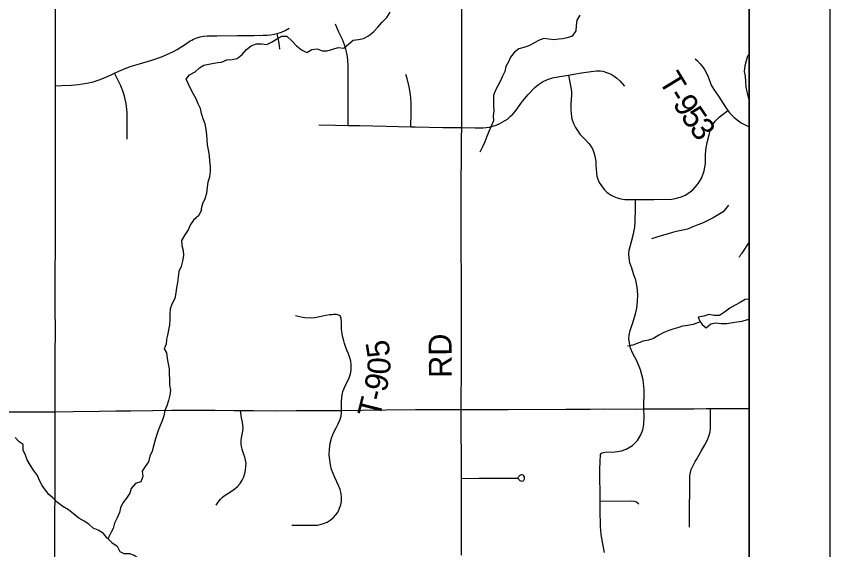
# Model space of a CAD drawing. Extents: x 0 to 34, y 0 to 22.
# Drawn here: x 7.992 to 9, y 14.845 to 15.506 of the extents above; entities that cross this region are included whole.
import ezdxf

# ---------------------------------------------------------------- set-up
doc = ezdxf.new("R2010")
doc.units = 0
for name, color, linetype in [('GM_X_County_Road', 7, 'Continuous'), ('GM_X_Minor_Lake', 7, 'Continuous'), ('GM_X_Minor_River', 7, 'Continuous'), ('GM_X_Rail_Line_Text', 7, 'Continuous'), ('GM_X_State_Route', 7, 'Continuous'), ('GM_X_Township_Road', 7, 'Continuous'), ('GM_X_Township_Road_Text', 7, 'Continuous'), ('SH_Cut_Line', 7, 'Continuous'), ('SH_Data', 7, 'Continuous')]:
    doc.layers.add(name, color=color, linetype=linetype)

msp = doc.modelspace()

# ---------------------------------------------------------------- linework, layer by layer
at = {"layer": 'GM_X_County_Road'}
msp.add_lwpolyline([(7.9697, 15.0163), (8.0251, 15.0165), (8.04, 15.0165), (8.0624, 15.0168), (8.0949, 15.0171), (8.115, 15.0174), (8.1338, 15.0177), (8.1608, 15.0181), (8.1843, 15.0183), (8.2118, 15.0183), (8.2383, 15.0182), (8.2619, 15.0181), (8.2697, 15.018), (8.2857, 15.0179), (8.3148, 15.0177), (8.339, 15.0178), (8.3602, 15.0181), (8.3808, 15.0181), (8.3948, 15.0181), (8.42, 15.0184), (8.4496, 15.0187), (8.4864, 15.019), (8.5076, 15.019), (8.5322, 15.0191), (8.5433, 15.0191), (8.5616, 15.0191), (8.6013, 15.0194), (8.6729, 15.0196), (8.7032, 15.0197), (8.7191, 15.0199), (8.7604, 15.0198), (8.7697, 15.0199), (8.7876, 15.02), (8.8317, 15.0202), (8.847, 15.0203), (8.8522, 15.0204), (8.88, 15.0206), (8.9, 15.0206)], dxfattribs=at)
at = {"layer": 'GM_X_Minor_Lake'}
for points in [[(8.9, 15.1557), (8.8951, 15.1555), (8.8889, 15.1516), (8.8827, 15.1483), (8.876, 15.1446), (8.8694, 15.1396), (8.8634, 15.1357), (8.8568, 15.1358), (8.8503, 15.1369), (8.8438, 15.1347), (8.837, 15.1335), (8.839, 15.1286)], [(8.839, 15.1286), (8.8419, 15.1246), (8.847, 15.1205), (8.8527, 15.1253), (8.8588, 15.1265), (8.8656, 15.1258), (8.8725, 15.1259), (8.885, 15.128), (8.8914, 15.1286), (8.8982, 15.1306), (8.9, 15.1309)], [(8.839, 15.1286), (8.8419, 15.1246), (8.847, 15.1205), (8.8527, 15.1253), (8.8588, 15.1265), (8.8656, 15.1258), (8.8725, 15.1259), (8.885, 15.128), (8.8914, 15.1286), (8.8982, 15.1306), (8.9, 15.1309)]]:
    msp.add_lwpolyline(points, dxfattribs=at)
at = {"layer": 'GM_X_Minor_River'}
for points in [[(8.2213, 15.2664), (8.2211, 15.2682), (8.223, 15.2746), (8.2259, 15.2807), (8.2278, 15.2872), (8.2289, 15.2942), (8.2295, 15.3011), (8.2316, 15.3074), (8.2323, 15.3142), (8.2323, 15.3207), (8.2315, 15.3271), (8.2311, 15.3338), (8.23, 15.3408), (8.2288, 15.3473), (8.2281, 15.3534), (8.2279, 15.3598), (8.2271, 15.3663), (8.2257, 15.373), (8.2233, 15.3794), (8.2214, 15.3859), (8.22, 15.392), (8.2172, 15.398), (8.2145, 15.4041), (8.2112, 15.41), (8.208, 15.4161), (8.2023, 15.4283), (8.2064, 15.434), (8.2133, 15.4376), (8.219, 15.4424), (8.2243, 15.446), (8.2302, 15.4469), (8.2367, 15.4483), (8.2414, 15.449), (8.2462, 15.4496), (8.2526, 15.4523), (8.2591, 15.453), (8.2656, 15.4542), (8.2715, 15.459), (8.277, 15.4651), (8.2827, 15.4696), (8.289, 15.4721), (8.2958, 15.4721), (8.3023, 15.4714), (8.3082, 15.4744), (8.3144, 15.4782), (8.3207, 15.4816), (8.3272, 15.4817), (8.3333, 15.4761), (8.339, 15.4699), (8.3451, 15.4649), (8.3519, 15.4617), (8.3582, 15.4653), (8.3647, 15.4661), (8.3708, 15.4635), (8.3772, 15.4638), (8.3839, 15.4658), (8.3907, 15.4679), (8.3976, 15.4669), (8.4037, 15.4724), (8.4094, 15.477), (8.4158, 15.4776), (8.4219, 15.4789), (8.4284, 15.482), (8.4343, 15.4873), (8.44, 15.4928), (8.4447, 15.4987), (8.4512, 15.505), (8.4552, 15.5115)], [(8.6901, 15.5078), (8.6865, 15.5015), (8.6856, 15.4946), (8.6852, 15.4882), (8.6808, 15.4819), (8.6747, 15.4796), (8.669, 15.4783), (8.6643, 15.4779), (8.658, 15.4773), (8.6455, 15.4788), (8.6392, 15.4765), (8.6331, 15.4731), (8.627, 15.47), (8.6207, 15.4676), (8.6147, 15.466), (8.6091, 15.4618), (8.6042, 15.4559), (8.6017, 15.4499), (8.5987, 15.444), (8.5972, 15.4381), (8.5943, 15.4324), (8.5919, 15.4263), (8.5887, 15.4202), (8.5852, 15.4141), (8.5833, 15.4084), (8.5832, 15.4019), (8.5832, 15.3953), (8.5838, 15.3892), (8.5828, 15.3829), (8.5834, 15.3768), (8.5802, 15.3703), (8.5775, 15.3635), (8.5749, 15.3574), (8.5724, 15.3508), (8.5697, 15.3447), (8.5663, 15.3382)], [(8.9, 15.4594), (8.8981, 15.4571), (8.8966, 15.4512), (8.8949, 15.4451), (8.8938, 15.4382), (8.8951, 15.4322), (8.8957, 15.4253), (8.8961, 15.4187), (8.8972, 15.413), (8.899, 15.4063), (8.9, 15.4019)], [(8.2213, 15.2664), (8.2179, 15.2597), (8.2113, 15.2539), (8.2075, 15.2483), (8.2048, 15.2418), (8.2006, 15.2357), (8.1964, 15.2288), (8.197, 15.2225), (8.1986, 15.2163), (8.1988, 15.21), (8.1976, 15.2031), (8.1961, 15.1963), (8.193, 15.19), (8.1925, 15.1831), (8.1916, 15.1766), (8.1904, 15.1698), (8.1893, 15.1637), (8.1882, 15.1568), (8.1847, 15.1499), (8.1825, 15.1438), (8.182, 15.1373), (8.1819, 15.1307), (8.1817, 15.1242), (8.1792, 15.1112), (8.1781, 15.1065), (8.1774, 15.1002), (8.1752, 15.0942), (8.1779, 15.0893), (8.1788, 15.0825), (8.18, 15.0757), (8.181, 15.0694), (8.1813, 15.0631), (8.1817, 15.0566), (8.1816, 15.0498), (8.1828, 15.0433), (8.1821, 15.0371), (8.1803, 15.0304), (8.1783, 15.0239), (8.1757, 15.0178), (8.1744, 15.0113), (8.1726, 15.0052), (8.1702, 14.9994), (8.1676, 14.9933), (8.1656, 14.9868), (8.1634, 14.98), (8.1616, 14.9738), (8.1603, 14.9674), (8.1573, 14.9612), (8.1557, 14.9544), (8.1514, 14.9486), (8.1476, 14.9429), (8.1485, 14.936), (8.1459, 14.9297), (8.1393, 14.9274), (8.1342, 14.9214), (8.1324, 14.9157), (8.1283, 14.9095), (8.1239, 14.9036), (8.121, 14.8975), (8.1197, 14.8914), (8.1169, 14.8849), (8.1134, 14.8784), (8.1119, 14.8719), (8.1095, 14.8671), (8.1062, 14.8608)], [(8.8745, 15.2723), (8.8681, 15.2642), (8.8556, 15.2568), (8.849, 15.2533), (8.8424, 15.2502), (8.8365, 15.248), (8.8304, 15.2457), (8.8238, 15.2426), (8.8181, 15.2412), (8.8117, 15.24), (8.8051, 15.2386), (8.7986, 15.2366), (8.7925, 15.2348), (8.7855, 15.2326), (8.7789, 15.2308)], [(8.8394, 15.1279), (8.8307, 15.1245), (8.8242, 15.1233), (8.8177, 15.1223), (8.8113, 15.1205), (8.8054, 15.1187), (8.8005, 15.1171), (8.7943, 15.1148), (8.7882, 15.1111), (8.7816, 15.107), (8.7752, 15.105), (8.7687, 15.1038), (8.7559, 15.0991), (8.7492, 15.0975)], [(8.1052, 14.8595), (8.1045, 14.8597), (8.0997, 14.8656), (8.0933, 14.8696), (8.087, 14.8722), (8.0817, 14.877), (8.0759, 14.881), (8.0692, 14.8847), (8.0627, 14.8898), (8.0564, 14.895), (8.0493, 14.8991), (8.0428, 14.904), (8.037, 14.9098), (8.0322, 14.914), (8.0278, 14.9194), (8.0237, 14.9251), (8.0204, 14.9313), (8.0181, 14.9376), (8.0129, 14.9442), (8.0092, 14.95), (8.0051, 14.9568), (8.0032, 14.9627), (8.0001, 14.969), (8.0004, 14.9758), (7.9952, 14.9792), (7.9904, 14.9845)], [(8.1062, 14.8608), (8.1052, 14.8594), (8.1101, 14.8542), (8.1168, 14.8499), (8.1202, 14.8434), (8.125, 14.8406), (8.1319, 14.8407), (8.138, 14.8385), (8.1439, 14.8346), (8.1502, 14.835), (8.1565, 14.8326), (8.1594, 14.8262), (8.1642, 14.8205), (8.1701, 14.8215), (8.1752, 14.8205), (8.1789, 14.8148), (8.1807, 14.8083), (8.1861, 14.8023), (8.1892, 14.7959), (8.1906, 14.789), (8.1945, 14.7795)]]:
    msp.add_lwpolyline(points, dxfattribs=at)
at = {"layer": 'GM_X_Rail_Line_Text'}
msp.add_lwpolyline([(6.7466, 14.1), (8.9, 14.1), (8.9, 15.6523), (8.8508, 15.6522), (8.8171, 15.6521), (8.5543, 15.6514), (8.3811, 15.6506), (8.0395, 15.6494), (7.5679, 15.6463), (7.4959, 15.6456), (7.4784, 15.6461), (7.1748, 15.6445), (6.9992, 15.644), (6.9828, 15.6433), (6.74, 15.6415), (6.7392, 15.6038), (6.74, 15.3491), (6.7393, 15.1276), (6.7414, 15.0209), (6.742, 15.0165), (6.7463, 14.3712), (6.7463, 14.3661)], close=True, dxfattribs=at)
at = {"layer": 'GM_X_State_Route'}
msp.add_lwpolyline([(8.039, 14.3885), (8.0391, 14.4039), (8.039, 14.4258), (8.0389, 14.4718), (8.039, 14.5651), (8.0391, 14.6718), (8.0391, 14.7062), (8.0393, 14.7709), (8.0394, 14.8374), (8.0396, 14.8572), (8.0398, 14.9446), (8.04, 15.0165), (8.0399, 15.05), (8.0399, 15.0891), (8.0401, 15.115), (8.04, 15.147), (8.04, 15.1627), (8.0402, 15.2454), (8.0403, 15.3623), (8.0402, 15.3923), (8.0402, 15.4202), (8.0401, 15.5518)], dxfattribs=at)
at = {"layer": 'GM_X_Township_Road'}
for points in [[(8.5433, 15.0191), (8.5434, 15.0771), (8.5436, 15.129), (8.5435, 15.1755), (8.5432, 15.2259), (8.5432, 15.2663), (8.5433, 15.297), (8.5436, 15.3349), (8.5437, 15.355), (8.5438, 15.3685), (8.544, 15.429), (8.544, 15.5026), (8.5441, 15.5209), (8.544, 15.5397), (8.5441, 15.5619), (8.5442, 15.5864), (8.5443, 15.6088), (8.5444, 15.6207), (8.5451, 15.6271), (8.5464, 15.631), (8.5479, 15.6352), (8.5517, 15.6446), (8.555, 15.6513)], [(8.0402, 15.4202), (8.0476, 15.4205), (8.0601, 15.421), (8.0686, 15.4218), (8.0792, 15.4237), (8.0868, 15.4254), (8.0958, 15.4282), (8.1028, 15.431), (8.1094, 15.4338), (8.1134, 15.4358), (8.119, 15.4383), (8.1238, 15.4405), (8.1329, 15.444), (8.1446, 15.4475), (8.1597, 15.4521), (8.173, 15.4567), (8.1783, 15.459), (8.1856, 15.4622), (8.1912, 15.4654), (8.2026, 15.4728), (8.2072, 15.4758), (8.2091, 15.4769), (8.2114, 15.478), (8.2154, 15.4796), (8.2198, 15.4809), (8.2237, 15.4816), (8.2283, 15.4821), (8.2405, 15.4823), (8.2658, 15.4826), (8.2863, 15.4828), (8.2976, 15.483), (8.3027, 15.4832), (8.3068, 15.4835), (8.3113, 15.4841), (8.315, 15.485), (8.3203, 15.4869), (8.325, 15.489), (8.3299, 15.4917)], [(8.4029, 15.3711), (8.403, 15.3865), (8.403, 15.4067), (8.4032, 15.4287), (8.4032, 15.4448), (8.4026, 15.4525), (8.4018, 15.4588), (8.3996, 15.4678), (8.3959, 15.4775), (8.3917, 15.4867), (8.3872, 15.4966)], [(8.3182, 15.4656), (8.3179, 15.47), (8.3173, 15.4751), (8.3161, 15.481), (8.315, 15.485)], [(8.833, 15.4539), (8.8357, 15.4516), (8.8392, 15.4477), (8.843, 15.4429), (8.8451, 15.4398), (8.8472, 15.4358), (8.8492, 15.4313), (8.8516, 15.4249), (8.8532, 15.4211), (8.8564, 15.4159), (8.8621, 15.4074), (8.8708, 15.3939), (8.8737, 15.3895), (8.8758, 15.3868), (8.8794, 15.3829), (8.8816, 15.3811), (8.8868, 15.3767), (8.8903, 15.3745), (8.8935, 15.3728), (8.8986, 15.3704), (8.9, 15.3699)], [(8.5438, 15.3685), (8.5604, 15.3683), (8.5706, 15.3684), (8.574, 15.3686), (8.5784, 15.3692), (8.5822, 15.3703), (8.5866, 15.3717), (8.591, 15.3734), (8.5967, 15.3768), (8.6006, 15.379), (8.6043, 15.3826), (8.6073, 15.3852), (8.6099, 15.3885), (8.6132, 15.3928), (8.6171, 15.3985), (8.6196, 15.4017), (8.6263, 15.4093), (8.6344, 15.4182), (8.6389, 15.422), (8.6439, 15.4252), (8.65, 15.4281), (8.6563, 15.4302), (8.6631, 15.4314), (8.6763, 15.4335), (8.6829, 15.4346), (8.6923, 15.4363), (8.7044, 15.4381), (8.7108, 15.4389), (8.7155, 15.4387), (8.7187, 15.4384), (8.7247, 15.4365), (8.7291, 15.4347), (8.733, 15.4324), (8.7363, 15.4298), (8.7397, 15.4265), (8.7455, 15.4198)], [(8.129, 15.3541), (8.1291, 15.3696), (8.129, 15.3865), (8.1286, 15.3919), (8.1278, 15.3978), (8.1261, 15.4057), (8.124, 15.4128), (8.1211, 15.4202), (8.1172, 15.4283), (8.1134, 15.4358)], [(8.4809, 15.3696), (8.481, 15.3869), (8.481, 15.3984), (8.4806, 15.4056), (8.4798, 15.4121), (8.4786, 15.4192), (8.4762, 15.4292), (8.4745, 15.4343)], [(8.6763, 15.4335), (8.6787, 15.4203), (8.6798, 15.4131), (8.6799, 15.4083), (8.6796, 15.4038), (8.679, 15.3976), (8.6789, 15.3912), (8.6793, 15.3856), (8.6805, 15.3794), (8.6825, 15.3737), (8.6847, 15.3688), (8.6872, 15.365), (8.6904, 15.3605), (8.6972, 15.3532), (8.7015, 15.3487), (8.704, 15.3454), (8.7059, 15.3421), (8.7075, 15.3377), (8.7088, 15.3329), (8.7099, 15.3271), (8.7102, 15.3219), (8.7108, 15.3121), (8.7114, 15.3085), (8.7125, 15.3046), (8.7144, 15.3003), (8.7169, 15.2962), (8.7206, 15.2916), (8.7238, 15.2886), (8.7284, 15.2852), (8.7323, 15.283), (8.7366, 15.2815), (8.7412, 15.2801), (8.7461, 15.2796), (8.7526, 15.2793), (8.7592, 15.2795), (8.7818, 15.2794), (8.8043, 15.2798), (8.8086, 15.2805), (8.8161, 15.2828), (8.8206, 15.2847), (8.8241, 15.2867), (8.8272, 15.2889), (8.8306, 15.2919), (8.8331, 15.2945), (8.8357, 15.2974), (8.8382, 15.3009), (8.841, 15.3059), (8.8433, 15.3113), (8.8444, 15.3151), (8.8453, 15.3196), (8.8459, 15.3242), (8.846, 15.3288), (8.8461, 15.3357), (8.8468, 15.3436), (8.8479, 15.3499), (8.8505, 15.3597), (8.8517, 15.3645), (8.8543, 15.3708), (8.8581, 15.3764), (8.8629, 15.3815), (8.8666, 15.3845), (8.872, 15.3884), (8.8737, 15.3895)], [(8.3668, 15.3718), (8.3873, 15.3714), (8.4029, 15.3711), (8.4174, 15.371), (8.4501, 15.3702), (8.4809, 15.3696), (8.486, 15.3695), (8.5205, 15.3688), (8.5389, 15.3685), (8.5438, 15.3685)], [(8.7697, 15.0199), (8.7698, 15.0437), (8.7687, 15.0558), (8.7655, 15.0684), (8.7609, 15.0793), (8.756, 15.0887), (8.7531, 15.0953), (8.7517, 15.1019), (8.7511, 15.107), (8.7514, 15.1112), (8.7527, 15.1171), (8.7542, 15.122), (8.7558, 15.1264), (8.7592, 15.1377), (8.7608, 15.1448), (8.7618, 15.1524), (8.7621, 15.1617), (8.7612, 15.1709), (8.7595, 15.1793), (8.7568, 15.1872), (8.7545, 15.1944), (8.7524, 15.2009), (8.7512, 15.207), (8.751, 15.2115), (8.7514, 15.2165), (8.7538, 15.2256), (8.7567, 15.2367), (8.7583, 15.245), (8.7589, 15.2521), (8.7591, 15.2681), (8.7592, 15.2795)], [(8.8876, 15.208), (8.8882, 15.2088), (8.8888, 15.2096), (8.8894, 15.2104), (8.89, 15.2112), (8.8906, 15.212), (8.8913, 15.2131), (8.9, 15.2262)], [(8.3948, 15.0181), (8.3949, 15.028), (8.3952, 15.0349), (8.3959, 15.0391), (8.3966, 15.0417), (8.3976, 15.0444), (8.3993, 15.0485), (8.4026, 15.0547), (8.4045, 15.0586), (8.4058, 15.0633), (8.4066, 15.068), (8.4068, 15.0708), (8.4067, 15.075), (8.4062, 15.0789), (8.4051, 15.0832), (8.4033, 15.088), (8.4013, 15.0928), (8.3996, 15.0973), (8.3985, 15.101), (8.3976, 15.1044), (8.3962, 15.11), (8.3957, 15.1129), (8.3952, 15.1161), (8.395, 15.1187), (8.3949, 15.1217), (8.3948, 15.124), (8.3948, 15.1287), (8.3946, 15.1302), (8.3945, 15.1314), (8.3942, 15.1329), (8.3937, 15.1341), (8.3934, 15.1347), (8.393, 15.1351), (8.3922, 15.1357), (8.3913, 15.1362), (8.39, 15.1366), (8.3887, 15.1368), (8.3869, 15.1369), (8.3849, 15.1368), (8.3833, 15.1367), (8.3799, 15.1363), (8.3754, 15.1355), (8.3715, 15.1347), (8.3617, 15.1326), (8.3561, 15.1323), (8.3495, 15.1328), (8.3448, 15.1336), (8.341, 15.1345), (8.3379, 15.1354)], [(8.2393, 14.9008), (8.2419, 14.9045), (8.245, 14.9079), (8.2475, 14.9105), (8.2505, 14.913), (8.2541, 14.9152), (8.2596, 14.9188), (8.2631, 14.9212), (8.2658, 14.9238), (8.2691, 14.9277), (8.2717, 14.9317), (8.2738, 14.9358), (8.2751, 14.9398), (8.2759, 14.9441), (8.2764, 14.9489), (8.2765, 14.9525), (8.2759, 14.9566), (8.2751, 14.9602), (8.2739, 14.9636), (8.2727, 14.967), (8.2717, 14.9699), (8.2709, 14.9735), (8.2706, 14.9766), (8.2705, 14.9805), (8.2709, 14.9842), (8.2716, 14.9883), (8.2726, 14.9925), (8.273, 14.9959), (8.272, 15.0034), (8.271, 15.009), (8.2699, 15.015), (8.2697, 15.018)], [(8.3334, 14.8758), (8.3438, 14.8757), (8.3576, 14.8758), (8.3649, 14.876), (8.3682, 14.8767), (8.3727, 14.878), (8.377, 14.8796), (8.3809, 14.8819), (8.3848, 14.8852), (8.3878, 14.8885), (8.3905, 14.8924), (8.3925, 14.8969), (8.3938, 14.9009), (8.3948, 14.9056), (8.3949, 14.91), (8.3943, 14.915), (8.3932, 14.9201), (8.391, 14.9251), (8.3864, 14.935), (8.3825, 14.9448), (8.3812, 14.9505), (8.3802, 14.9567), (8.3797, 14.9627), (8.38, 14.97), (8.3809, 14.9776), (8.3826, 14.9838), (8.385, 14.9902), (8.3883, 14.9965), (8.3908, 15.0014), (8.3927, 15.0058), (8.3943, 15.0111), (8.3948, 15.0153), (8.3948, 15.0181)], [(8.5435, 14.8385), (8.5436, 14.898), (8.5436, 14.9339), (8.5433, 15.0191)], [(8.7209, 14.8421), (8.7182, 14.8549), (8.7166, 14.8643), (8.7158, 14.8741), (8.7155, 14.8948), (8.7153, 14.9056), (8.7152, 14.9454), (8.7158, 14.9635), (8.7171, 14.9649), (8.7196, 14.9661), (8.7233, 14.9666), (8.7305, 14.9664), (8.737, 14.967), (8.742, 14.9679), (8.7475, 14.9699), (8.7556, 14.9747), (8.7616, 14.9809), (8.7659, 14.9876), (8.7684, 14.9939), (8.7697, 15.0006), (8.7699, 15.0102), (8.7697, 15.0199)], [(8.826, 14.8735), (8.8262, 14.8847), (8.8264, 14.9312), (8.8266, 14.9368), (8.8273, 14.9413), (8.8283, 14.9449), (8.8296, 14.9475), (8.8331, 14.9546), (8.8348, 14.9572), (8.8407, 14.9676), (8.8453, 14.9755), (8.8484, 14.9817), (8.8507, 14.9873), (8.8516, 14.9915), (8.8521, 14.9956), (8.8523, 15.0091), (8.8522, 15.0161), (8.8522, 15.0204)], [(8.5436, 14.9339), (8.5652, 14.934), (8.6121, 14.9342), (8.6135, 14.9338), (8.6141, 14.9332), (8.6148, 14.9324), (8.6158, 14.9313), (8.617, 14.9307), (8.6184, 14.9305), (8.6199, 14.9309), (8.621, 14.9316), (8.6217, 14.9331), (8.6217, 14.9342), (8.6215, 14.9357), (8.6208, 14.937), (8.6201, 14.9377), (8.6189, 14.9381), (8.6177, 14.9382), (8.6167, 14.938), (8.6157, 14.9374), (8.6151, 14.9368), (8.6142, 14.9355), (8.6131, 14.9341)], [(8.7153, 14.9056), (8.7541, 14.9062), (8.7574, 14.9058), (8.7605, 14.9047), (8.7633, 14.9024)]]:
    msp.add_lwpolyline(points, dxfattribs=at)
at = {"layer": 'SH_Cut_Line'}
msp.add_lwpolyline([(2.1, 14.1), (8.9, 14.1), (8.9, 20.5212), (8.8849, 20.5209), (8.7884, 20.5191), (8.452, 20.5125), (8.417, 20.5122), (8.3939, 20.5118), (8.3832, 20.5112), (8.3787, 20.5111), (8.375, 20.511), (8.1885, 20.5062), (7.9577, 20.5026), (7.7441, 20.5018), (7.5555, 20.4983), (7.4108, 20.4954), (7.1285, 20.4898), (7.05, 20.4883), (6.9911, 20.4871)], dxfattribs=at)
at = {"layer": 'SH_Data'}
for p, q in [((9, 21), (9, 14)), ((8.9, 20.9), (8.9, 14.1))]:
    msp.add_line(p, q, dxfattribs=at)

# ---------------------------------------------------------------- texts
at = {"layer": 'GM_X_Township_Road_Text'}
for s, height, rotation, p in [('T', 0.0284, 301.3276, (8.7873, 15.4267)), ('-', 0.0284, 301.4801, (8.7984, 15.4084)), ('9', 0.0284, 302.0698, (8.8047, 15.3982)), ('5', 0.0284, 303.9539, (8.8145, 15.3825)), ('3', 0.0284, 306.3379, (8.825, 15.367)), ('5', 0.0284, 98.8056, (8.4556, 15.0861)), ('RD', 0.02841, 90.4937, (8.5316, 15.0585)), ('0', 0.0284, 86.0656, (8.4547, 15.0618)), ('9', 0.0284, 76.6098, (8.4499, 15.0397)), ('T', 0.0284, 76.0895, (8.4419, 15.0075)), ('-', 0.0284, 76.1655, (8.447, 15.0282))]:
    msp.add_text(s, height=height, rotation=rotation, dxfattribs=at).set_placement(p)

doc.saveas('drawing.dxf')
